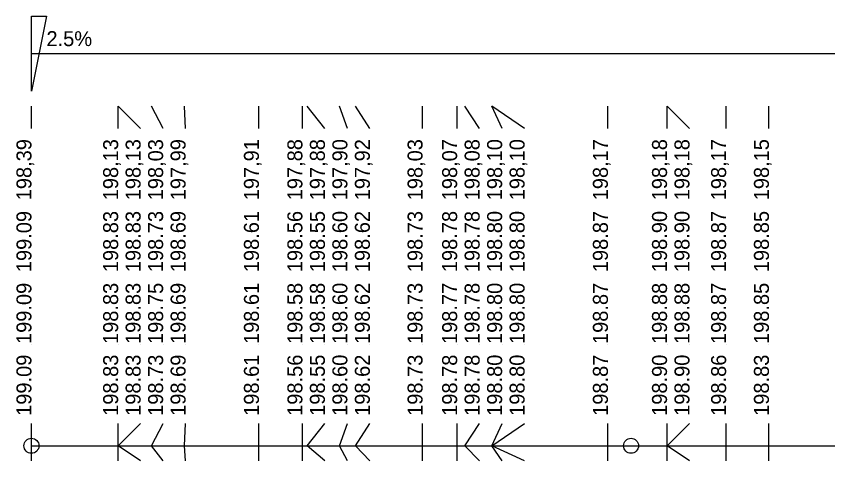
# Model space of a CAD drawing. Extents: x -51 to 53, y -74 to 15.
# Drawn here: x -38.69 to -25.16, y -6.7 to 0.72 of the extents above; entities that cross this region are included whole.
import ezdxf

# ---------------------------------------------------------------- set-up
doc = ezdxf.new("R2010")
doc.units = 0
for name, color, linetype in [('KOTY_L', 7, 'Continuous'), ('KOTY_N', 7, 'Continuous'), ('KOTY_S', 7, 'Continuous'), ('KOTY_T', 7, 'Continuous'), ('KOTY_VP', 7, 'Continuous'), ('Nová vrstva (0)', 7, 'Continuous'), ('PR_SKLON_L', 7, 'Continuous'), ('PR_SKLON_T', 7, 'Continuous'), ('ROVINA_L', 7, 'Continuous'), ('ROVINA_O', 7, 'Continuous')]:
    doc.layers.add(name, color=color, linetype=linetype)

msp = doc.modelspace()

# ---------------------------------------------------------------- linework, layer by layer
at = {"layer": 'KOTY_L'}
for p, q in [((-38.44, -1.151), (-38.44, -0.776)), ((-36.994, -1.151), (-36.994, -0.776)), ((-36.619, -1.151), (-36.994, -0.776)), ((-36.244, -1.151), (-36.44, -0.776)), ((-35.869, -1.151), (-35.886, -0.776)), ((-34.646, -1.151), (-34.646, -0.776)), ((-33.921, -1.151), (-33.921, -0.776)), ((-33.546, -1.151), (-33.84, -0.776)), ((-33.171, -1.151), (-33.3, -0.776)), ((-32.796, -1.151), (-33.034, -0.776)), ((-31.917, -1.151), (-31.917, -0.776)), ((-31.34, -1.151), (-31.34, -0.776)), ((-30.965, -1.151), (-31.213, -0.776)), ((-30.59, -1.151), (-30.763, -0.776)), ((-30.215, -1.151), (-30.763, -0.776)), ((-28.826, -1.151), (-28.826, -0.776)), ((-27.84, -1.151), (-27.84, -0.776)), ((-27.465, -1.151), (-27.84, -0.776)), ((-26.854, -1.151), (-26.854, -0.776)), ((-26.14, -1.151), (-26.14, -0.776)), ((-38.44, -4.751), (-38.44, -4.751)), ((-36.994, -4.751), (-36.994, -4.751)), ((-36.619, -4.751), (-36.619, -4.751)), ((-36.244, -4.751), (-36.244, -4.751)), ((-35.869, -4.751), (-35.869, -4.751)), ((-34.646, -4.751), (-34.646, -4.751)), ((-33.921, -4.751), (-33.921, -4.751)), ((-33.546, -4.751), (-33.546, -4.751)), ((-33.171, -4.751), (-33.171, -4.751)), ((-32.796, -4.751), (-32.796, -4.751)), ((-31.917, -4.751), (-31.917, -4.751)), ((-31.34, -4.751), (-31.34, -4.751)), ((-30.965, -4.751), (-30.965, -4.751)), ((-30.59, -4.751), (-30.59, -4.751)), ((-30.215, -4.751), (-30.215, -4.751)), ((-28.826, -4.751), (-28.826, -4.751)), ((-27.84, -4.751), (-27.84, -4.751)), ((-27.465, -4.751), (-27.465, -4.751)), ((-26.854, -4.751), (-26.854, -4.751)), ((-26.14, -4.751), (-26.14, -4.751)), ((-38.44, -6.451), (-38.44, -6.076)), ((-36.994, -6.451), (-36.994, -6.076)), ((-36.994, -6.451), (-36.619, -6.076)), ((-36.44, -6.451), (-36.244, -6.076)), ((-35.886, -6.451), (-35.869, -6.076)), ((-34.646, -6.451), (-34.646, -6.076)), ((-33.921, -6.451), (-33.921, -6.076)), ((-33.84, -6.451), (-33.546, -6.076)), ((-33.3, -6.451), (-33.171, -6.076)), ((-33.034, -6.451), (-32.796, -6.076)), ((-31.917, -6.451), (-31.917, -6.076)), ((-31.34, -6.451), (-31.34, -6.076)), ((-31.213, -6.451), (-30.965, -6.076)), ((-30.763, -6.451), (-30.59, -6.076)), ((-30.763, -6.451), (-30.215, -6.076)), ((-28.826, -6.451), (-28.826, -6.076)), ((-27.84, -6.451), (-27.84, -6.076)), ((-27.84, -6.451), (-27.465, -6.076)), ((-26.854, -6.451), (-26.854, -6.076)), ((-26.14, -6.451), (-26.14, -6.076))]:
    msp.add_line(p, q, dxfattribs=at)
at = {"layer": 'KOTY_S'}
for p, q in [((-38.44, -6.701), (-38.44, -6.451)), ((-36.994, -6.701), (-36.994, -6.451)), ((-36.619, -6.701), (-36.994, -6.451)), ((-36.244, -6.701), (-36.44, -6.451)), ((-35.869, -6.701), (-35.886, -6.451)), ((-34.646, -6.701), (-34.646, -6.451)), ((-33.921, -6.701), (-33.921, -6.451)), ((-33.546, -6.701), (-33.84, -6.451)), ((-33.171, -6.701), (-33.3, -6.451)), ((-32.796, -6.701), (-33.034, -6.451)), ((-31.917, -6.701), (-31.917, -6.451)), ((-31.34, -6.701), (-31.34, -6.451)), ((-30.965, -6.701), (-31.213, -6.451)), ((-30.59, -6.701), (-30.763, -6.451)), ((-30.215, -6.701), (-30.763, -6.451)), ((-28.826, -6.701), (-28.826, -6.451)), ((-27.84, -6.701), (-27.84, -6.451)), ((-27.465, -6.701), (-27.84, -6.451)), ((-26.854, -6.701), (-26.854, -6.451)), ((-26.14, -6.701), (-26.14, -6.451))]:
    msp.add_line(p, q, dxfattribs=at)
at = {"layer": 'PR_SKLON_L'}
msp.add_line((-38.44, 0.099), (-11.54, 0.099), dxfattribs=at)
msp.add_lwpolyline([(-38.44, 0.099), (-38.44, 0.724), (-38.19, 0.724), (-38.44, -0.526)], close=True, dxfattribs=at)
at = {"layer": 'ROVINA_L'}
msp.add_line((-38.44, -6.451), (50.86, -6.451), dxfattribs=at)
at = {"layer": 'ROVINA_O'}
for centre in [(-38.44, -6.451), (-28.44, -6.451)]:
    msp.add_circle(centre, 0.125, dxfattribs=at)

# ---------------------------------------------------------------- texts
at = {"layer": 'KOTY_N'}
for s, p in [('199.09', (-38.44, -4.751)), ('198.83', (-36.994, -4.751)), ('198.83', (-36.619, -4.751)), ('198.75', (-36.244, -4.751)), ('198.69', (-35.869, -4.751)), ('198.61', (-34.646, -4.751)), ('198.58', (-33.921, -4.751)), ('198.58', (-33.546, -4.751)), ('198.60', (-33.171, -4.751)), ('198.62', (-32.796, -4.751)), ('198.73', (-31.917, -4.751)), ('198.77', (-31.34, -4.751)), ('198.78', (-30.965, -4.751)), ('198.80', (-30.59, -4.751)), ('198.80', (-30.215, -4.751)), ('198.87', (-28.826, -4.751)), ('198.88', (-27.84, -4.751)), ('198.88', (-27.465, -4.751)), ('198.87', (-26.854, -4.751)), ('198.85', (-26.14, -4.751))]:
    msp.add_text(s, height=0.25, rotation=90, dxfattribs=at).set_placement(p)
at = {"layer": 'KOTY_T'}
for s, p in [('199.09', (-38.44, -5.951)), ('198.83', (-36.994, -5.951)), ('198.83', (-36.619, -5.951)), ('198.73', (-36.244, -5.951)), ('198.69', (-35.869, -5.951)), ('198.61', (-34.646, -5.951)), ('198.56', (-33.921, -5.951)), ('198.55', (-33.546, -5.951)), ('198.60', (-33.171, -5.951)), ('198.62', (-32.796, -5.951)), ('198.73', (-31.917, -5.951)), ('198.78', (-31.34, -5.951)), ('198.78', (-30.965, -5.951)), ('198.80', (-30.59, -5.951)), ('198.80', (-30.215, -5.951)), ('198.87', (-28.826, -5.951)), ('198.90', (-27.84, -5.951)), ('198.90', (-27.465, -5.951)), ('198.86', (-26.854, -5.951)), ('198.83', (-26.14, -5.951))]:
    msp.add_text(s, height=0.25, rotation=90, dxfattribs=at).set_placement(p)
at = {"layer": 'KOTY_VP'}
for s, p in [('199.09', (-38.44, -3.551)), ('198.83', (-36.994, -3.551)), ('198.83', (-36.619, -3.551)), ('198.73', (-36.244, -3.551)), ('198.69', (-35.869, -3.551)), ('198.61', (-34.646, -3.551)), ('198.56', (-33.921, -3.551)), ('198.55', (-33.546, -3.551)), ('198.60', (-33.171, -3.551)), ('198.62', (-32.796, -3.551)), ('198.73', (-31.917, -3.551)), ('198.78', (-31.34, -3.551)), ('198.78', (-30.965, -3.551)), ('198.80', (-30.59, -3.551)), ('198.80', (-30.215, -3.551)), ('198.87', (-28.826, -3.551)), ('198.90', (-27.84, -3.551)), ('198.90', (-27.465, -3.551)), ('198.87', (-26.854, -3.551)), ('198.85', (-26.14, -3.551))]:
    msp.add_text(s, height=0.25, rotation=90, dxfattribs=at).set_placement(p)
at = {"layer": 'Nová vrstva (0)'}
for s, p in [('198,39', (-38.44, -2.351)), ('198,13', (-36.994, -2.351)), ('198,13', (-36.619, -2.351)), ('198,03', (-36.244, -2.351)), ('197,99', (-35.869, -2.351)), ('197,91', (-34.646, -2.351)), ('197,88', (-33.921, -2.351)), ('197,88', (-33.546, -2.351)), ('197,90', (-33.171, -2.351)), ('197,92', (-32.796, -2.351)), ('198,03', (-31.917, -2.351)), ('198,07', (-31.34, -2.351)), ('198,08', (-30.965, -2.351)), ('198,10', (-30.59, -2.351)), ('198,10', (-30.215, -2.351)), ('198,17', (-28.826, -2.351)), ('198,18', (-27.84, -2.351)), ('198,18', (-27.465, -2.351)), ('198,17', (-26.854, -2.351)), ('198,15', (-26.14, -2.351))]:
    msp.add_text(s, height=0.25, rotation=90, dxfattribs=at).set_placement(p)
at = {"layer": 'PR_SKLON_T'}
msp.add_text('2.5%', height=0.25, dxfattribs=at).set_placement((-38.19, 0.224))

doc.saveas('drawing.dxf')
